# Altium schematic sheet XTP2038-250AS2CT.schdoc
size 127 x 101 mm
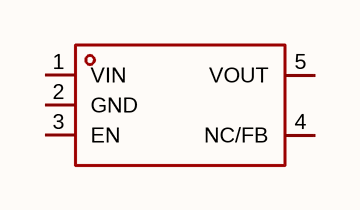
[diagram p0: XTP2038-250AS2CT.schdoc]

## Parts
U?  xtp2038-250as2ct  [TSOT-23-5_L2.9-W1.6-P0.95-LS2.8-BR]  (value not drawn)

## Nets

Not connected (* = marked no-connect by the designer): U? 1(VIN) 2(GND) 3(EN) 4(NC/FB) 5(VOUT)

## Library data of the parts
U? = xtp2038-250as2ct: 输出极性:正极;工作电压:5.5V;输出电压:2.5V;输出电流:500mA;电源纹波抑制比(PSRR):-;输出类型:固定;; Manufacturer: XTX(芯天下); AddInBom: yes; ModelId: b5108020abe84f7bb0f3c398b43b6e0b; ModelName: TSOT-23-5_L2.9-W1.6-H1.00-LS2.8-P0.95; ModelTransform: 110.45568,114.173,0,180,0,0,0,0,0; Output Configuration: 正极; Voltage - Supply: 5.5V; Output Voltage: 2.5V; Output Current: 500mA; Voltage Dropout: 180mV@(300mA); standby current: 15uA; Output Type: 固定; Number of Outputs: 1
